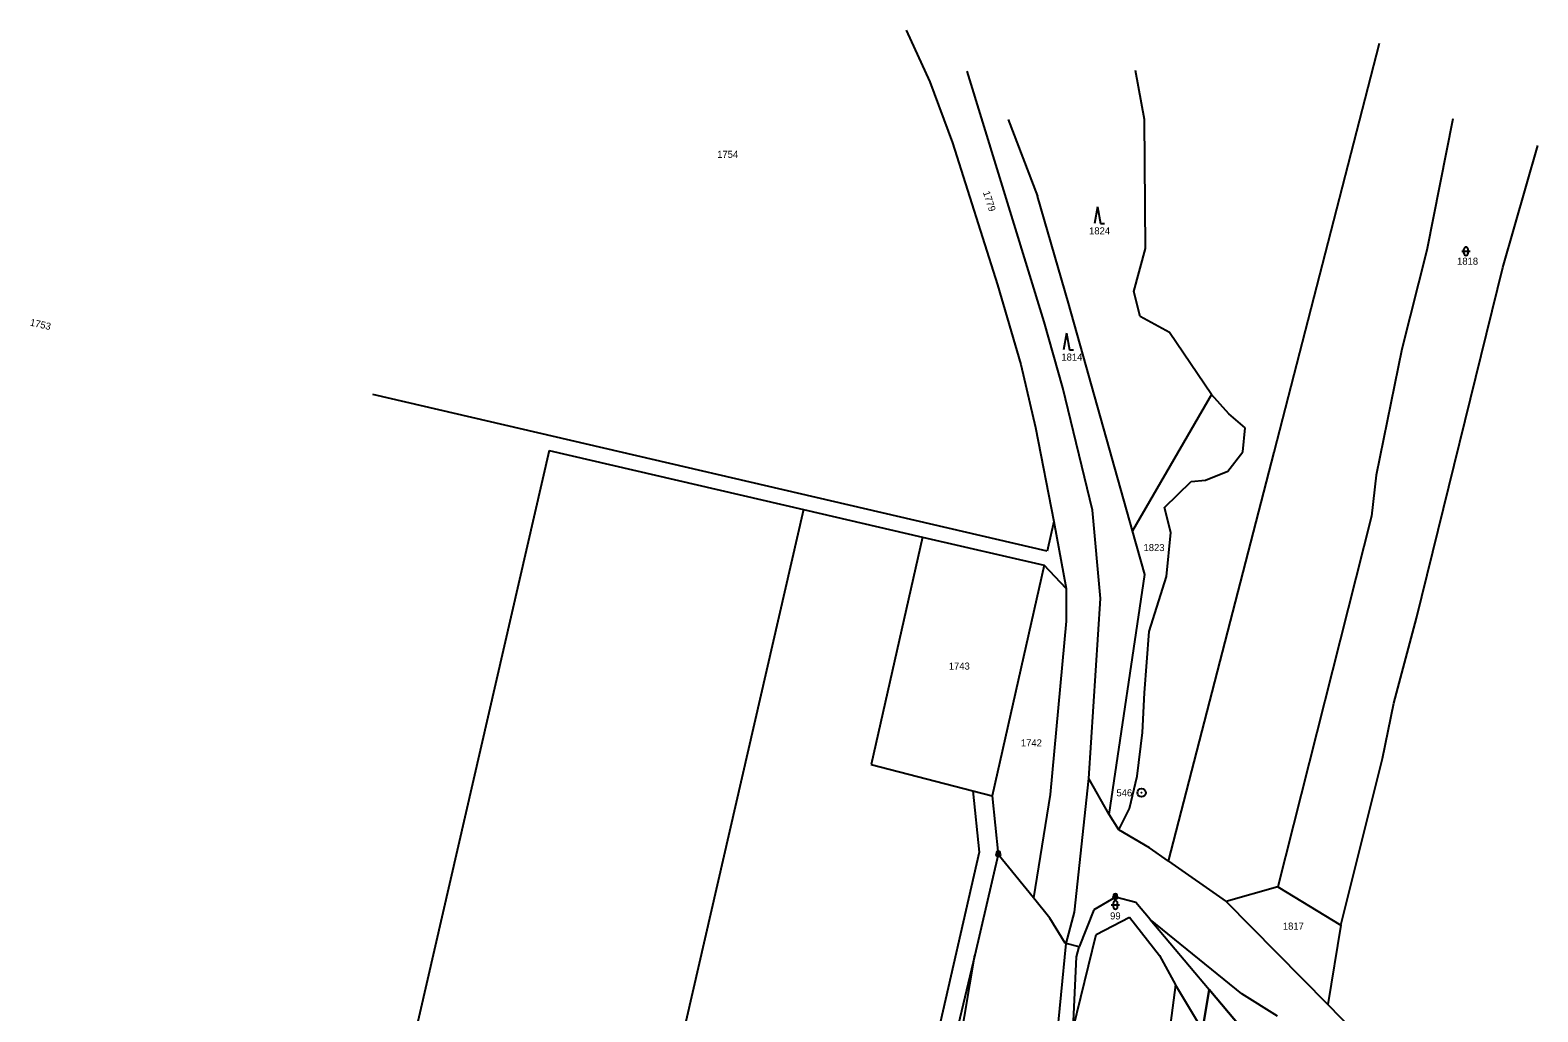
# Model space of a CAD drawing. Extents: x -801826 to -800592, y -1032871 to -1031813.
# Drawn here: x -801821.3 to -801458.4, y -1032050.6 to -1031814.4 of the extents above; entities that cross this region are included whole.
import ezdxf

# ---------------------------------------------------------------- set-up
doc = ezdxf.new("R2010")
doc.units = 0
for name, color, linetype in [('Vrstva 1', 7, 'Continuous'), ('Vrstva 17', 7, 'Continuous'), ('Vrstva 18', 7, 'Continuous'), ('Vrstva 24', 7, 'Continuous'), ('Vrstva 25', 7, 'Continuous')]:
    doc.layers.add(name, color=color, linetype=linetype)

msp = doc.modelspace()

# ---------------------------------------------------------------- linework, layer by layer
at = {"layer": 'Vrstva 1'}
for p, q in [((-801610.42, -1031814.36), (-801604.75, -1031826.83)), ((-801521.9, -1031915.9), (-801496.51, -1031817.48)), ((-801577.25, -1031884.52), (-801595.75, -1031824.24)), ((-801553.06, -1031835.83), (-801555.28, -1031824.04)), ((-801604.75, -1031826.83), (-801599.27, -1031841.48)), ((-801478.9, -1031835.7), (-801485.09, -1031867.33)), ((-801585.87, -1031835.86), (-801578.82, -1031854.3)), ((-801552.86, -1031866.9), (-801553.06, -1031835.83)), ((-801599.27, -1031841.48), (-801588.46, -1031875.61)), ((-801466.85, -1031871.49), (-801458.4, -1031842.1)), ((-801571.4, -1031880.09), (-801578.82, -1031854.3)), ((-801555.65, -1031877.22), (-801552.86, -1031866.9)), ((-801485.09, -1031867.33), (-801491.12, -1031891.16)), ((-801487.58, -1031955.86), (-801466.85, -1031871.49)), ((-801588.46, -1031875.61), (-801582.81, -1031894.78)), ((-801554.1, -1031883.26), (-801555.65, -1031877.22)), ((-801555.96, -1031934.82), (-801571.4, -1031880.09)), ((-801572.76, -1031900.4), (-801577.25, -1031884.52)), ((-801547.05, -1031887.13), (-801554.1, -1031883.26)), ((-801536.98, -1031902.04), (-801547.05, -1031887.13)), ((-801491.12, -1031891.16), (-801497.29, -1031921.44)), ((-801582.81, -1031894.78), (-801579.27, -1031909.94)), ((-801565.63, -1031929.87), (-801572.76, -1031900.4)), ((-801576.48, -1031939.72), (-801738.81, -1031902.05)), ((-801536.98, -1031902.04), (-801555.96, -1031934.82)), ((-801532.77, -1031906.7), (-801536.98, -1031902.04)), ((-801528.82, -1031910.06), (-801532.77, -1031906.7)), ((-801579.27, -1031909.94), (-801574.88, -1031932.6)), ((-801529.41, -1031915.85), (-801528.82, -1031910.06)), ((-801696.39, -1031915.49), (-801735.27, -1032084.52)), ((-801696.39, -1031915.49), (-801635.15, -1031929.7)), ((-801547.3, -1032014.33), (-801521.9, -1031915.9)), ((-801533.03, -1031920.47), (-801529.41, -1031915.85)), ((-801541.83, -1031923), (-801538.39, -1031922.66)), ((-801538.39, -1031922.66), (-801533.03, -1031920.47)), ((-801497.29, -1031921.44), (-801498.46, -1031931.32)), ((-801548.28, -1031929.22), (-801541.83, -1031923)), ((-801635.15, -1031929.7), (-801673.2, -1032095.09)), ((-801635.15, -1031929.7), (-801606.53, -1031936.35)), ((-801563.64, -1031951.11), (-801565.63, -1031929.87)), ((-801546.77, -1031935.23), (-801548.28, -1031929.22)), ((-801574.88, -1031932.6), (-801576.48, -1031939.72)), ((-801574.88, -1031932.6), (-801571.92, -1031948.71)), ((-801498.46, -1031931.32), (-801521, -1032020.51)), ((-801606.53, -1031936.35), (-801618.85, -1031991.11)), ((-801606.53, -1031936.35), (-801577.25, -1031943.14)), ((-801553, -1031945.32), (-801555.96, -1031934.82)), ((-801547.81, -1031945.84), (-801546.77, -1031935.23)), ((-801577.25, -1031943.14), (-801589.73, -1031998.6)), ((-801571.92, -1031948.71), (-801577.25, -1031943.14)), ((-801561.56, -1032003.12), (-801553, -1031945.32)), ((-801551.93, -1031959.07), (-801547.81, -1031945.84)), ((-801571.92, -1031948.71), (-801571.89, -1031956.61)), ((-801566.45, -1031994.44), (-801563.64, -1031951.11)), ((-801571.89, -1031956.61), (-801575.76, -1031998.26)), ((-801553.11, -1031973.85), (-801551.93, -1031959.07)), ((-801493.04, -1031976.3), (-801487.58, -1031955.86)), ((-801553.53, -1031983.39), (-801553.11, -1031973.85)), ((-801495.83, -1031989.67), (-801493.04, -1031976.3)), ((-801554.87, -1031993.91), (-801553.53, -1031983.39)), ((-801618.85, -1031991.11), (-801594.38, -1031997.4)), ((-801505.8, -1032029.73), (-801495.83, -1031989.67)), ((-801569.89, -1032026.59), (-801566.45, -1031994.44)), ((-801561.56, -1032003.12), (-801566.45, -1031994.44)), ((-801556.68, -1032001.68), (-801554.87, -1031993.91)), ((-801594.38, -1031997.4), (-801592.85, -1032012.2)), ((-801594.38, -1031997.4), (-801589.73, -1031998.6)), ((-801589.73, -1031998.6), (-801588.27, -1032012.76)), ((-801575.76, -1031998.26), (-801579.82, -1032023.18)), ((-801559.22, -1032006.82), (-801556.68, -1032001.68)), ((-801559.22, -1032006.82), (-801561.56, -1032003.12)), ((-801551.86, -1032011.15), (-801559.22, -1032006.82)), ((-801592.85, -1032012.2), (-801618.6, -1032124.34)), ((-801588.27, -1032012.76), (-801593.88, -1032036.96)), ((-801579.82, -1032023.18), (-801588.27, -1032012.76)), ((-801547.3, -1032014.33), (-801551.86, -1032011.15)), ((-801547.3, -1032014.33), (-801533.38, -1032024.02)), ((-801521, -1032020.51), (-801533.38, -1032024.02)), ((-801521, -1032020.51), (-801505.8, -1032029.73)), ((-801575.88, -1032028.03), (-801579.82, -1032023.18)), ((-801560.09, -1032023.03), (-801565.3, -1032026.06)), ((-801555.17, -1032024.29), (-801560.09, -1032023.03)), ((-801551.74, -1032028.36), (-801555.17, -1032024.29)), ((-801508.93, -1032048.86), (-801533.38, -1032024.02)), ((-801572.16, -1032034.1), (-801575.88, -1032028.03)), ((-801571.93, -1032034.16), (-801569.89, -1032026.59)), ((-801565.3, -1032026.06), (-801568.81, -1032034.92)), ((-801564.72, -1032031.99), (-801556.7, -1032027.85)), ((-801556.7, -1032027.85), (-801549.5, -1032037.05)), ((-801529.66, -1032046.3), (-801551.74, -1032028.36)), ((-801551.74, -1032028.36), (-801537.52, -1032045.21)), ((-801505.8, -1032029.73), (-801508.93, -1032048.86)), ((-801575.66, -1032072.95), (-801571.93, -1032034.16)), ((-801571.93, -1032034.16), (-801572.16, -1032034.1)), ((-801568.81, -1032034.92), (-801571.93, -1032034.16)), ((-801570.22, -1032054.57), (-801564.72, -1032031.99)), ((-801569.48, -1032037.37), (-801568.81, -1032034.92)), ((-801593.88, -1032036.96), (-801615.22, -1032125.41)), ((-801600.19, -1032074.16), (-801593.88, -1032036.96)), ((-801570.22, -1032054.57), (-801569.48, -1032037.37)), ((-801549.5, -1032037.05), (-801545.6, -1032044.06)), ((-801545.6, -1032044.06), (-801555.21, -1032116.05)), ((-801539.15, -1032054.89), (-801545.6, -1032044.06)), ((-801539.15, -1032054.89), (-801537.52, -1032045.21)), ((-801537.52, -1032045.21), (-801539.15, -1032054.89)), ((-801537.52, -1032045.21), (-801529.87, -1032054.28)), ((-801529.87, -1032054.28), (-801537.52, -1032045.21)), ((-801521.04, -1032051.65), (-801529.66, -1032046.3)), ((-801484.98, -1032073.21), (-801508.93, -1032048.86))]:
    msp.add_line(p, q, dxfattribs=at)
at = {"layer": 'Vrstva 24'}
for centre, radius in [((-801553.79, -1031997.88), 1), ((-801553.79, -1031997.88), 0.0439), ((-801588.27, -1032012.76), 0.5), ((-801588.27, -1032012.76), 0.0364), ((-801560.09, -1032023.03), 0.5), ((-801560.09, -1032023.03), 0.0364)]:
    msp.add_circle(centre, radius, dxfattribs=at)
for centre in [(-801588.27, -1032012.39), (-801560.09, -1032022.66)]:
    msp.add_arc(centre, 0.45, 344.4473, 196.3778, dxfattribs=at)
at = {"layer": 'Vrstva 25'}
for p, q in [((-801564.4, -1031856.9), (-801565.14, -1031860.9)), ((-801564.4, -1031856.9), (-801563.67, -1031860.9)), ((-801563.67, -1031860.9), (-801562.67, -1031860.9)), ((-801476.71, -1031867.56), (-801474.71, -1031867.56)), ((-801476.21, -1031868.06), (-801476.21, -1031867.06)), ((-801475.21, -1031868.06), (-801475.21, -1031867.06)), ((-801571.87, -1031887.3), (-801572.6, -1031891.3)), ((-801571.87, -1031887.3), (-801571.14, -1031891.3)), ((-801571.14, -1031891.3), (-801570.14, -1031891.3)), ((-801560.57, -1032025.38), (-801560.57, -1032024.38)), ((-801559.57, -1032025.38), (-801559.57, -1032024.38)), ((-801561.07, -1032024.88), (-801559.07, -1032024.88))]:
    msp.add_line(p, q, dxfattribs=at)
for centre, start, end in [((-801475.71, -1031867.06), 0, 180), ((-801475.71, -1031868.06), 180, 0), ((-801560.07, -1032024.38), 0, 180), ((-801560.07, -1032025.38), 180, 0)]:
    msp.add_arc(centre, 0.5, start, end, dxfattribs=at)

# ---------------------------------------------------------------- texts
at = {"layer": 'Vrstva 17'}
msp.add_text('546', height=1.7, dxfattribs=at).set_placement((-801559.83, -1031998.73))
at = {"layer": 'Vrstva 18'}
for s, p in [('1754', (-801655.93, -1031845.09)), ('1824', (-801566.42, -1031863.51)), ('1818', (-801477.84, -1031870.81)), ('1814', (-801573.08, -1031893.88)), ('1823', (-801553.31, -1031939.72)), ('1743', (-801600.18, -1031968.24)), ('1742', (-801582.83, -1031986.73)), ('99', (-801561.35, -1032028.36)), ('1817', (-801519.78, -1032030.81))]:
    msp.add_text(s, height=1.7, dxfattribs=at).set_placement(p)
for s, rotation, p in [('1779', 288.0259, (-801591.99, -1031853.36)), ('1753', 347.1551, (-801821.45, -1031885.43))]:
    msp.add_text(s, height=1.7, rotation=rotation, dxfattribs=at).set_placement(p)

doc.saveas('drawing.dxf')
